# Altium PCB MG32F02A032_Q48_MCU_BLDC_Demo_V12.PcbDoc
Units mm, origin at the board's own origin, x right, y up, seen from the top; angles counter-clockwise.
Board outline 44 x 36.5 mm, 2 copper layers (TopLayer, BottomLayer); 27 components, 57 nets, 200 pads, 107 vias.
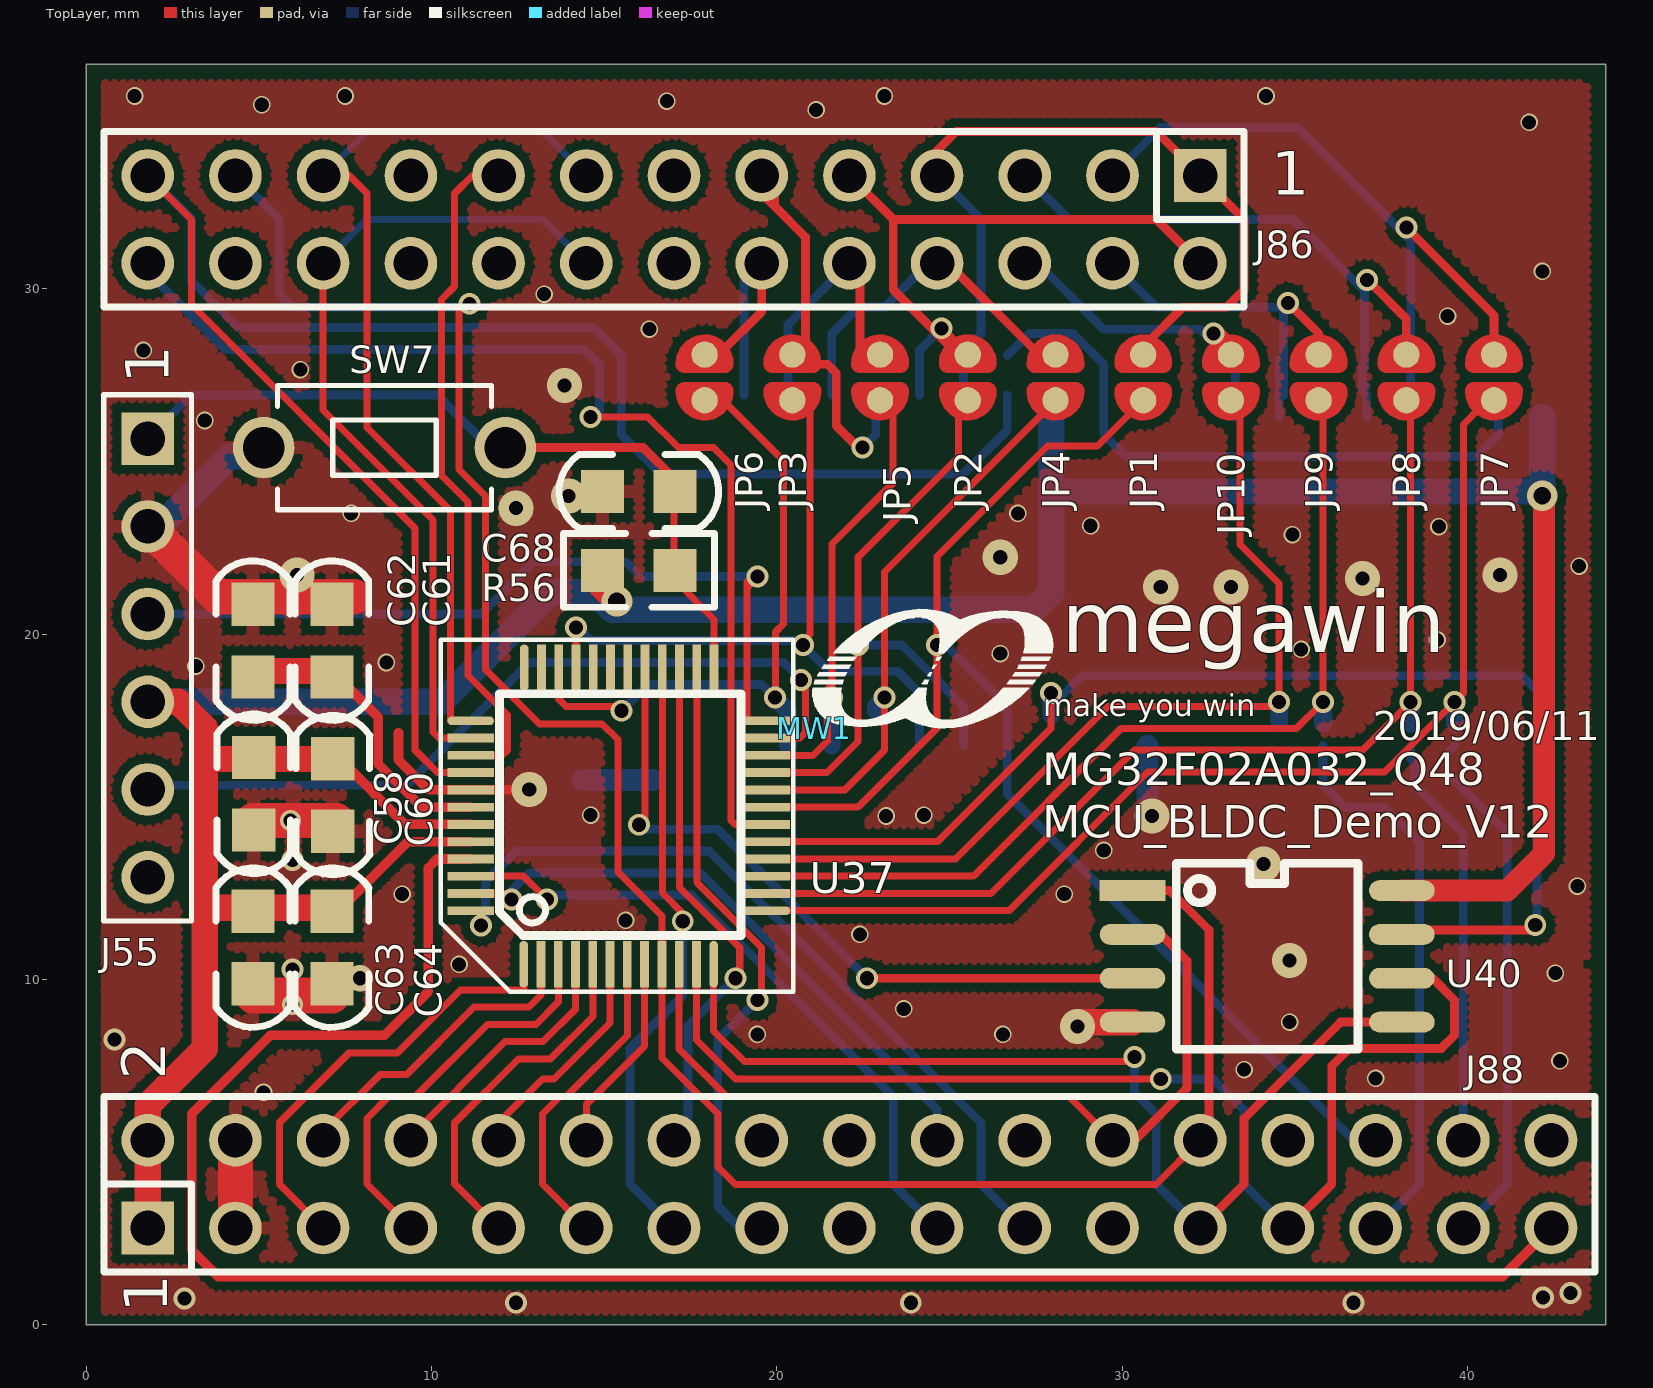
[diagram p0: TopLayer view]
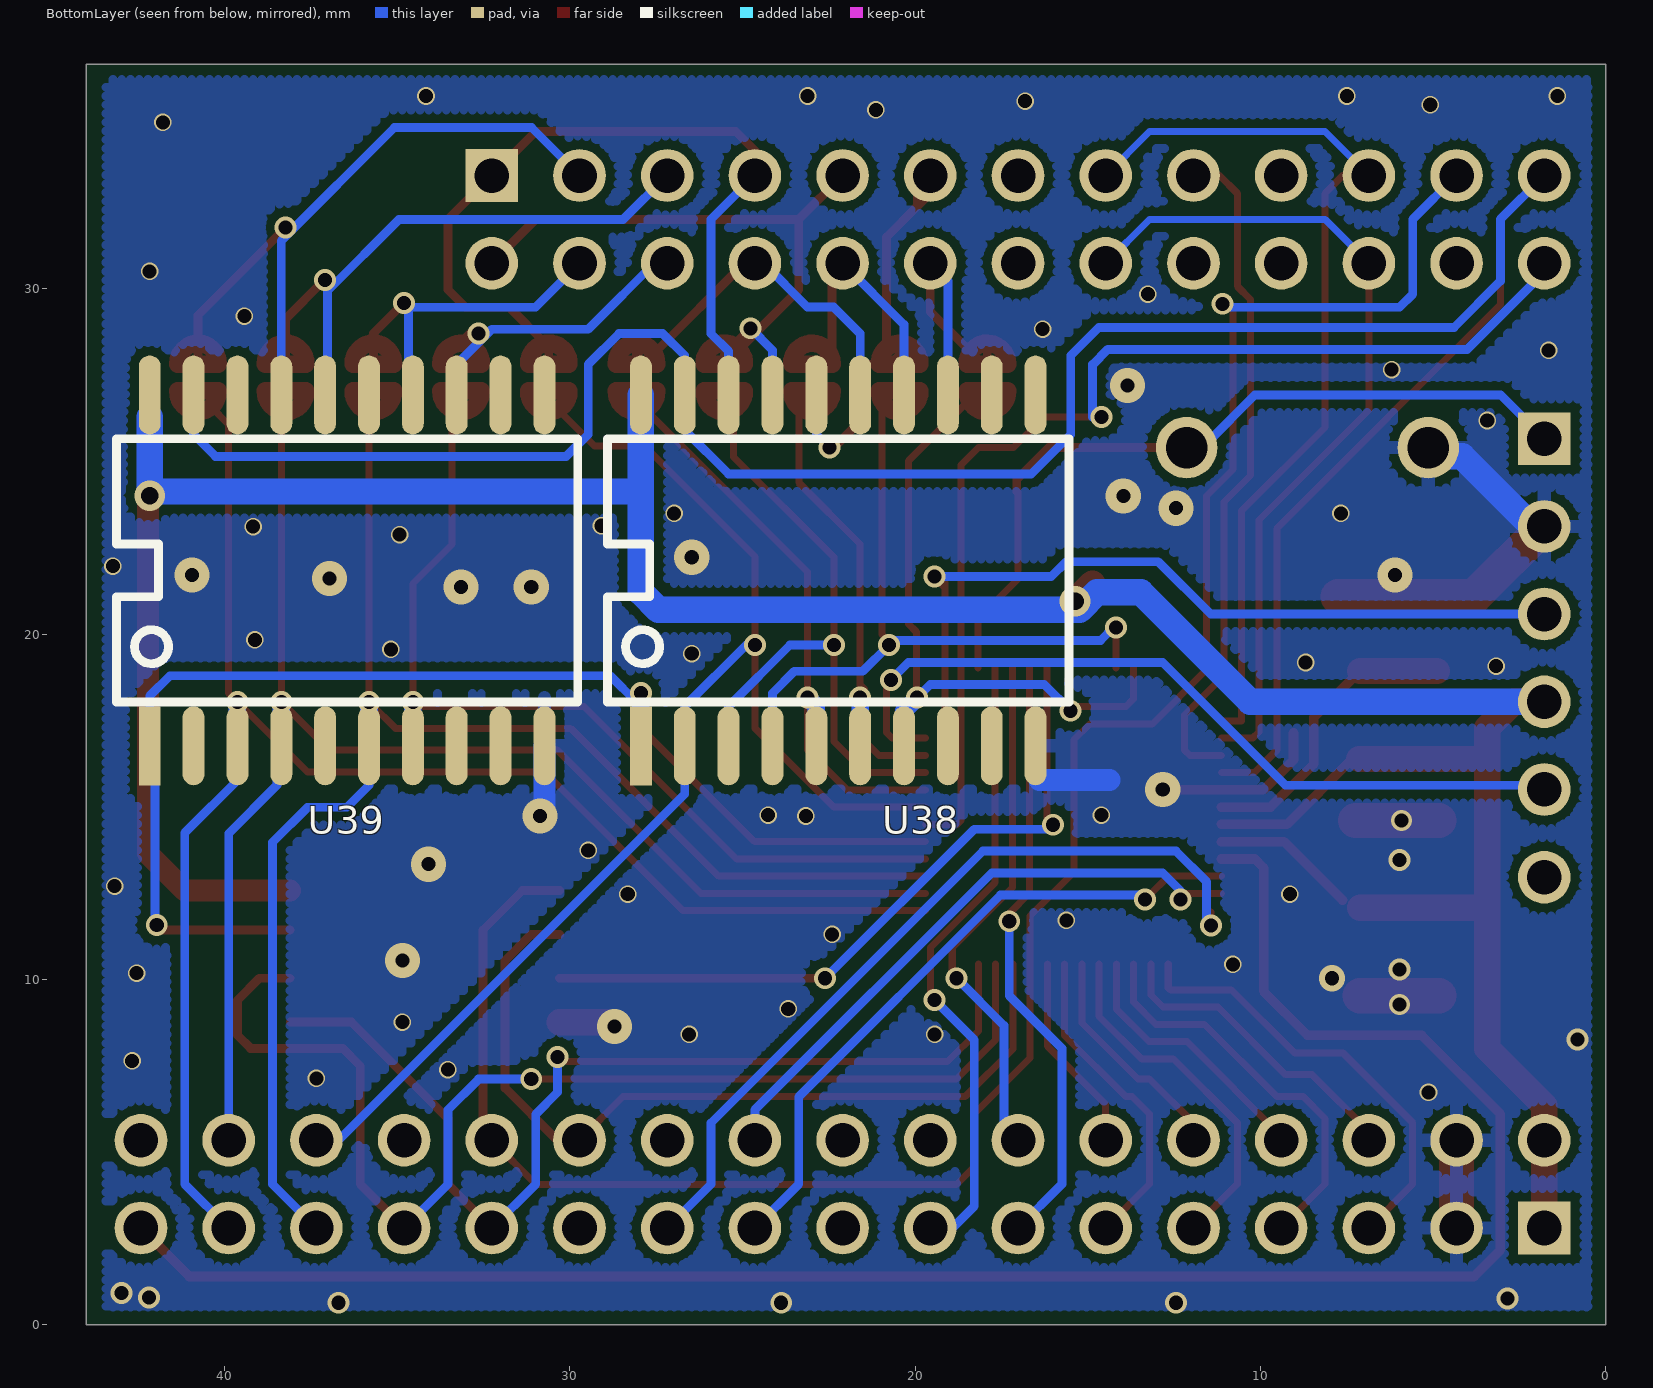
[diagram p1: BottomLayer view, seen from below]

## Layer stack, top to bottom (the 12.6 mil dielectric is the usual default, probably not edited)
TopLayer: signal copper 0.0356
Dielectric: dielectric 0.32, FR-4, Dk 4.8
BottomLayer: signal copper 0.0356

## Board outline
0,0 0,36.5 44,36.5 44,0

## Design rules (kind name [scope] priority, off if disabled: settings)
Clearance 12 [All] p1 off: gap=0.305
Clearance 10 [All] p2 off: gap=0.254
Clearance 6 [All] p3: gap=0.152
FabricationTestPointUsage TestPointUsage [All] p1: valid=0 allowmultiple=FALSE
FabricationTestpoint Testpoint [All] p1: side=3 testpointundercomponent=TRUE minsize=1.016 maxsize=2.54 preferedsize=1.524 minholesize=0.508 maxholesize=1.016 preferedholesize=0.813 testpointgrid=0.025 allowsidetop=TRUE allowsidebottom=TRUE usegrid=TRUE gridtolerance=0
HoleSize [All] p1: absolutevalues=TRUE maxlimit=12.7 minlimit=0.025 maxpercent=80.000 minpercent=20.000
PolygonConnect VIA [isvia] p1: connectstyle=Direct reliefconductorwidth=0.254 reliefentries=4 polygonreliefangle="90 Angle"
PolygonConnect PolygonConnect_1 [All] p2: connectstyle=Relief reliefconductorwidth=0.381 reliefentries=4 polygonreliefangle="90 Angle"
RoomDefinition MG32F02A032_Q48_MCU_BLDC_Demo_V12 [InComponentClass('MG32F02A032_Q48_MCU_BLDC_Demo_V12')] p1: confinementstyle=ConfineIn formatcopy=TRUE lockcomponents=FALSE outline -454.355,-362.943 -403.555,-362.943 -403.555,-337.543 -454.355,-337.543
RoutingPriority [All] p1: routingpriority=4
RoutingVias [All] p1: holewidth=0.406 width=0.635 viastyle="Through Hole" minholewidth=0.406 minwidth=0.61 maxholewidth=0.711 maxwidth=1.27
SilkscreenOverComponentPads [All] p1: minsilkscreentomaskgap=0.254
SolderMaskExpansion [All] p1: expansion=0.102
Width [All] p1: maxlimit=2.54 minlimit=0.203 preferedwidth=0.254
23 further rules are at their usual default settings.

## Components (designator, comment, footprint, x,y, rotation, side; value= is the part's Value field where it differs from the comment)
C58 "10u" 0805C 4.85,15.373 r270 top
C60 "0.1u" 0805C 7.136,15.339 r270 top
C61 "0.1u" 0805C 7.112,19.812 r90 top
C62 "4.7u" 0805C 4.826,19.812 r90 top
C63 "10u" 0805C 4.826,10.922 r270 top
C64 "0.1u" 0805C 7.112,10.922 r270 top
C68 "4.7u" 0805C 16.002,24.13 r180 top
J55 "ICE/Writer" PS6P254 1.778,25.66 r270 top
J86 "CON26A" PS13X2P254 32.258,33.28 r180 top locked
J88 "CON34A" PS17X2P254 1.778,2.8 r0 top locked
JP1 "SP" JUMP2C_SMD_1#1 30.607,27.432 r90 top
JP2 "SP" JUMP2C_SMD_1#2 25.527,27.432 r90 top
JP3 "SP" JUMP2C_SMD_1#3 20.447,27.432 r90 top
JP4 "SP" JUMP2C_SMD_1#4 28.067,27.432 r90 top
JP5 "SP" JUMP2C_SMD_1#5 22.987,27.432 r90 top
JP6 "SP" JUMP2C_SMD_1#6 17.907,27.432 r90 top
JP7 "SP" JUMP2C_SMD_1#7 40.767,27.432 r90 top
JP8 "SP" JUMP2C_SMD_1#8 38.227,27.432 r90 top
JP9 "SP" JUMP2C_SMD_1#9 35.687,27.432 r90 top
JP10 "SP" JUMP2C_SMD_1#10 33.147,27.432 r90 top
MW1 "MW-A4" MEGAWIN_3.4 21.082,17.272 r0 top
R56 "47K" 0805R 16.002,21.844 r0 top
SW7 "SW PUSHBUTTON" SW_T_2P 8.636,25.4 r180 top
U37 "MG32F02A032 QFP48" LQFP48_7X7_050 15.418,14.732 r0 top locked
U38 "74HC245/20P/SOIC" SO20_300P127 22.225,21.844 r180 bottom locked
U39 "74HC245/20P/SOIC" SO20_300P127 36.449,21.844 r180 bottom locked (schematic designator U38)
U40 "MX25L3206E/8-PIN SOP (200mil)" SO8_208P127 34.197,10.668 r270 top

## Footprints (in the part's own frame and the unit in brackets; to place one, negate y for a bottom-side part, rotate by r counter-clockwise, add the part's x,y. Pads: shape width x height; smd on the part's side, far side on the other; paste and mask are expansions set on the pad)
0805C [mm]
  rect 1.25x1.25 smd: 1(-1.05,0) 2(1.05,0)
  silkscreen extent -2.31,-1.07 2.31,1.07
0805R [mm]
  rect 1.25x1.25 smd: 1(-1.05,0) 2(1.05,0)
  silkscreen extent -2.18,-1.07 2.18,1.07
JUMP2C_SMD_1#1 [mil]
  round 30 smd: 1(-26,0) 2(26,0)
  TopLayer lines w20: -16,23 ccw(c-16,0) -29.57,18.57 ccw(c-16,0) -33.44,15 ccw(c-16,0) -34.57,13.57 ccw(c-16,0) -36.48,10.48 ccw(c-16,0) -38.45,5 ccw(c-16,0) -39,0 ccw(c-16,0) -16,-23 -15,-23 -15,0 -15,23 -16,23 ; 15,23 16,23 cw(c16,0) 26,20.71 cw(c16,0) 29.57,18.57 cw(c16,0) 34.57,13.57 cw(c16,0) 36.48,10.48 cw(c16,0) 38.7,-3.7 cw(c16,0) 36.48,-10.48 cw(c16,0) 16,-23 15,-23 15,0 15,23
JUMP2C_SMD_1#2 [mil]
  round 30 smd: 1(-26,0) 2(26,0)
  TopLayer lines w20: -16,23 ccw(c-16,0) -27.36,20 ccw(c-16,0) -33.44,15 ccw(c-16,0) -36.48,10.48 ccw(c-16,0) -36.71,10 ccw(c-16,0) -38.45,5 ccw(c-16,0) -39,0 ccw(c-16,0) -16,-23 -15,-23 -15,0 -15,15 -15,23 -16,23 ; 15,23 16,23 cw(c16,0) 26,20.71 cw(c16,0) 31.76,16.76 cw(c16,0) 33.44,15 cw(c16,0) 36.48,10.48 cw(c16,0) 38.45,5 cw(c16,0) 39,0 cw(c16,0) 26,-20.71 cw(c16,0) 16,-23 15,-23 15,0 15,23
JUMP2C_SMD_1#3 [mil]
  round 30 smd: 1(-26,0) 2(26,0)
  TopLayer lines w20: -16,23 ccw(c-16,0) -36.48,10.48 ccw(c-16,0) -38.9,2.1 ccw(c-16,0) -38.83,-2.83 ccw(c-16,0) -37.93,-6.93 ccw(c-16,0) -36.48,-10.48 ccw(c-16,0) -27.36,-20 ccw(c-16,0) -26,-20.71 ccw(c-16,0) -16,-23 -15,-23 -15,-20 -15,0 -15,23 -16,23 ; 15,23 15,20 15,0 15,-11 15,-15 15,-23 16,-23 ccw(c16,0) 28.98,-18.98 ccw(c16,0) 33.44,-15 ccw(c16,0) 36.48,-10.48 ccw(c16,0) 37.93,-6.93 ccw(c16,0) 38.9,2.1 ccw(c16,0) 36.48,10.48 ccw(c16,0) 27.36,20 ccw(c16,0) 16,23 15,23
JUMP2C_SMD_1#4 [mil]
  round 30 smd: 1(-26,0) 2(26,0)
  TopLayer lines w20: -16,23 ccw(c-16,0) -33.44,15 ccw(c-16,0) -36.71,10 ccw(c-16,0) -38.45,5 ccw(c-16,0) -39,0 ccw(c-16,0) -16,-23 -15,-23 -15,0 -15,15 -15,23 -16,23 ; 15,23 15,0 15,-23 16,-23 ccw(c16,0) 26,-20.71 ccw(c16,0) 39,0 ccw(c16,0) 36.48,10.48 ccw(c16,0) 36,11.36 ccw(c16,0) 27.36,20 ccw(c16,0) 26,20.71 ccw(c16,0) 16,23 15,23
JUMP2C_SMD_1#5 [mil]
  round 30 smd: 1(-26,0) 2(26,0)
  TopLayer lines w20: -16,23 ccw(c-16,0) -39,0 ccw(c-16,0) -33.44,-15 ccw(c-16,0) -16,-23 -15,-23 -15,-15 -15,0 -15,23 -16,23 ; 15,23 16,23 cw(c16,0) 29.12,-18.89 cw(c16,0) 16,-23 15,-23 15,0 15,23
JUMP2C_SMD_1#6 [mil]
  round 30 smd: 1(-26,0) 2(26,0)
  TopLayer lines w20: -16,23 ccw(c-16,0) -26,20.71 ccw(c-16,0) -38.96,1.33 ccw(c-16,0) -37.75,-7.47 ccw(c-16,0) -36.48,-10.48 ccw(c-16,0) -34.27,-13.98 ccw(c-16,0) -31.76,-16.76 ccw(c-16,0) -29.15,-18.87 ccw(c-16,0) -26,-20.71 ccw(c-16,0) -17.92,-22.92 ccw(c-16,0) -16,-23 -15,-23 -15,-20 -15,-11 -15,0 -15,23 -16,23 ; 15,23 15,0 15,-5 15,-23 16,-23 ccw(c16,0) 28.98,-18.98 ccw(c16,0) 36.48,-10.48 ccw(c16,0) 37.74,-7.5 ccw(c16,0) 38.73,-3.5 ccw(c16,0) 39,0 ccw(c16,0) 37.75,7.49 ccw(c16,0) 16,23 15,23
JUMP2C_SMD_1#7 [mil]
  round 30 smd: 1(-26,0) 2(26,0)
  TopLayer lines w20: -16,23 ccw(c-16,0) -33.44,15 ccw(c-16,0) -38.45,5 ccw(c-16,0) -39,0 ccw(c-16,0) -16,-23 -15,-23 -15,0 -15,23 -16,23 ; 15,23 15,0 15,-23 16,-23 ccw(c16,0) 39,0 ccw(c16,0) 38.45,5 ccw(c16,0) 38.16,6.16 ccw(c16,0) 33.44,15 ccw(c16,0) 16,23 15,23
JUMP2C_SMD_1#8 [mil]
  round 30 smd: 1(-26,0) 2(26,0)
  TopLayer lines w20: -16,23 ccw(c-16,0) -38.9,2.1 ccw(c-16,0) -39,0 ccw(c-16,0) -38.45,-5 ccw(c-16,0) -37.93,-6.93 ccw(c-16,0) -36.48,-10.48 ccw(c-16,0) -16,-23 -15,-23 -15,0 -15,23 -16,23 ; 15,23 15,0 15,-23 16,-23 ccw(c16,0) 39,0 ccw(c16,0) 16,23 15,23
JUMP2C_SMD_1#9 [mil]
  round 30 smd: 1(-26,0) 2(26,0)
  TopLayer lines w20: -16,23 ccw(c-16,0) -33.44,15 ccw(c-16,0) -38.45,5 ccw(c-16,0) -39,0 ccw(c-16,0) -38.45,-5 ccw(c-16,0) -16,-23 -15,-23 -15,0 -15,23 -16,23 ; 15,23 16,23 cw(c16,0) 39,0 cw(c16,0) 16,-23 15,-23 15,0 15,23
JUMP2C_SMD_1#10 [mil]
  round 30 smd: 1(-26,0) 2(26,0)
  TopLayer lines w20: -16,23 ccw(c-16,0) -33.44,15 ccw(c-16,0) -38.45,5 ccw(c-16,0) -38.9,2.1 ccw(c-16,0) -39,0 ccw(c-16,0) -37.93,-6.93 ccw(c-16,0) -36.48,-10.48 ccw(c-16,0) -16,-23 -15,-23 -15,0 -15,23 -16,23 ; 15,23 16,23 cw(c16,0) 28.98,18.98 cw(c16,0) 36.48,10.48 cw(c16,0) 30.5,-17.85 cw(c16,0) 16,-23 15,-23 15,0 15,23
LQFP48_7X7_050 [mm]
  oval 0.254x1.35 smd: 1(-2.75,-4.292) 12(2.75,-4.292) 36(-2.737,4.292)
  rect 0.254x1.35 smd: 2(-2.25,-4.292) 3(-1.75,-4.292) 4(-1.25,-4.292) 5(-0.75,-4.292) 6(-0.25,-4.292) 7(0.25,-4.292) 8(0.75,-4.292) 9(1.25,-4.292) 10(1.75,-4.292) 11(2.25,-4.292) 25(2.763,4.292) 26(2.263,4.292) 27(1.763,4.292) 28(1.263,4.292) 29(0.763,4.292) 30(0.263,4.292) 31(-0.237,4.292) 32(-0.737,4.292) 33(-1.237,4.292) 34(-1.737,4.292) 35(-2.237,4.292)
  oval 1.35x0.254 smd: 13(4.286,-2.744) 37(-4.286,2.756)
  rect 1.35x0.254 smd: 14(4.286,-2.244) 15(4.286,-1.744) 16(4.286,-1.244) 17(4.286,-0.744) 18(4.286,-0.244) 19(4.286,0.256) 20(4.286,0.756) 21(4.286,1.256) 22(4.286,1.756) 23(4.286,2.256) 24(4.286,2.756) 38(-4.286,2.256) 39(-4.286,1.756) 40(-4.286,1.256) 41(-4.286,0.756) 42(-4.286,0.256) 43(-4.286,-0.244) 44(-4.286,-0.744) 45(-4.286,-1.244) 46(-4.286,-1.744) 47(-4.286,-2.244) 48(-4.286,-2.744)
  silkscreen extent -5.15,-5.09 5.05,5.11
MEGAWIN_3.4 [mm]
  silkscreen extent -0.05,0.01 6.92,3.44
PS6P254 [mil]
  rect 60x60 hole 39.37: 1(0,0)
  round 60 hole 39.37: 2(100,0) 3(200,0) 4(300,0) 5(400,0) 6(500,0)
  silkscreen extent -50,-50 550,50
PS13X2P254 [mil]
  rect 60x60 hole 39.37: 1(0,0)
  round 60 hole 39.37: 2(0,100) 3(100,0) 4(100,100) 5(200,0) 6(200,100) 7(300,0) 8(300,100) 9(400,0) 10(400,100) 11(500,0) 12(500,100) 13(600,0) 14(600,100) 15(700,0) 16(700,100) 17(800,0) 18(800,100) 19(900,0) 20(900,100) 21(1000,0) 22(1000,100) 23(1100,0) 24(1100,100) 25(1200,0) 26(1200,100)
  silkscreen extent -50,-50 1250,150
PS17X2P254 [mil]
  rect 60x60 hole 39.37: 1(0,0)
  round 60 hole 39.37: 2(0,100) 3(100,0) 4(100,100) 5(200,0) 6(200,100) 7(300,0) 8(300,100) 9(400,0) 10(400,100) 11(500,0) 12(500,100) 13(600,0) 14(600,100) 15(700,0) 16(700,100) 17(800,0) 18(800,100) 19(900,0) 20(900,100) 21(1000,0) 22(1000,100) 23(1100,0) 24(1100,100) 25(1200,0) 26(1200,100) 27(1300,0) 28(1300,100) 29(1400,0) 30(1400,100) 31(1500,0) 32(1500,100) 33(1600,0) 34(1600,100)
  silkscreen extent -50,-50 1650,150
SO8_208P127 [mm]
  rect 0.6x1.9 smd: 1(-1.905,-3.9)
  oval 0.6x1.9 smd: 2(-0.635,-3.9) 3(0.635,-3.9) 4(1.905,-3.9) 5(1.905,3.9) 6(0.635,3.9) 7(-0.635,3.9) 8(-1.905,3.9)
  silkscreen extent -2.69,-2.63 2.69,2.63
SO20_300P127 [mil]
  rect 25x90 smd: 1(-225,-200)
  oval 25x90 smd: 2(-175,-200) 3(-125,-200) 4(-75,-200) 5(-25,-200) 6(25,-200) 7(75,-200) 8(125,-200) 9(175,-200) 10(225,-200) 11(225,200) 12(175,200) 13(125,200) 14(75,200) 15(25,200) 16(-25,200) 17(-75,200) 18(-125,200) 19(-175,200) 20(-225,200)
  silkscreen extent -263,-150 263,150
SW_T_2P [mm]
  round 1.778 hole 1.2: 1(-3.5,0) 2(3.5,0)
  silkscreen extent -3.1,-1.8 3.1,1.8

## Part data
C58 C60 C61 C62 C63 C64 C68: library part "CAP NP"
J55: library part CON6
MW1: library part MW_A4_1
R56: library part RESISTOR
U37: library part IC-MG32F02A-LQFP48
U38 U39: library part 74HC245_0
U40: library part MX25L3206E

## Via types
v1: diameter 0.508, hole 0.406, TopLayer to BottomLayer, tented both sides, 45 vias
v2: diameter 0.635, hole 0.406, TopLayer to BottomLayer, tented both sides, 43 vias
v3: diameter 1.016, hole 0.406, TopLayer to BottomLayer, tented both sides, 14 vias
v4: diameter 0.889, hole 0.508, TopLayer to BottomLayer, tented both sides, 2 vias
v5: diameter 0.61, hole 0.406, TopLayer to BottomLayer, tented both sides, 2 vias
v6: diameter 0.762, hole 0.406, TopLayer to BottomLayer, tented both sides, 1 vias

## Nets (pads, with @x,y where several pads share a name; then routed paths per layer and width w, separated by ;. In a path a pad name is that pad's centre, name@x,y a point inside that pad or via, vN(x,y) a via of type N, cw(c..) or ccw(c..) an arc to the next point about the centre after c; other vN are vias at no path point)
74HC245_DIR: U37.17 U38.1 U39.1 U40.7 | length 36.1
  TopLayer w0.203: U37.17 24.656,13.988 27.94,17.272 v2@27.94,18.034
  TopLayer w0.254: U40.7@38.097,11.43 v2@41.961,11.43
  BottomLayer w0.254: v2@28.067,18.034 28.829,18.796 41.579,18.796 42.164,18.211 U39.1 ; v2@42.012,11.58 U39.1@42.012,16.764
  BottomLayer w0.508: U38.1@27.94,17.653 v2(27.94,18.288)
  other v2: 41.961,11.58
ACM_UH: J86.1 J86.7 JP1.2 U38.18 | length 23.6
  TopLayer w0.254: J86.7@24.279,33.639 25.196,34.556 30.982,34.556 J86.1 33.528,32.01 33.528,29.972 33.02,29.464 31.75,29.464 30.701,28.415 30.607,28.321 JP1.2
  BottomLayer w0.254: J86.7 25.908,32.01 25.908,28.702 25.4,28.194 U38.18
ACM_UL: J86.8 JP4.2 U38.15 | length 11.9
  TopLayer w0.254: J86.8@24.638,31.242 J86.8 24.946,30.74 27.559,28.127 ; JP4.2@27.801,28.358 JP4.2 JP4.2@28.067,28.423
  BottomLayer w0.254: U38.15 21.59,28.702 22.358,29.47 23.114,29.47 24.384,30.74 J86.8 ; J86.8@24.384,30.486 J86.8 ; J86.8@24.638,31.369 J86.8
ACM_VH: J86.2 J86.9 JP2.2 U38.17 | length 19.3
  TopLayer w0.254: J86.9 23.368,32.01 ; 25.102,28.238 25.101,28.239 v2@24.484,28.856 ; JP2.2 25.261,28.358 v2(24.763,28.856) v2@24.484,28.856 ; J86.2 30.988,32.01 23.368,32.01 ; 23.368,32.01 23.368,29.972 v2@24.484,28.856
  BottomLayer w0.254: U38.17 24.13,28.222 v2(24.763,28.856)
ACM_VL: J86.10 JP5.2 U38.14 | length 7.8
  TopLayer w0.254: J86.10@22.098,30.124 J86.10 ; 22.403,27.838 J86.10@22.403,30.48
  BottomLayer w0.254: U38.14 20.32,28.962 J86.10
ACM_WH: J86.11 JP3.2 U38.16 | length 11.7
  TopLayer w0.254: J86.11@19.558,32.766 19.939,32.385 ; 19.939,32.379 19.939,32.385 ; J86.11@19.939,32.893 19.939,32.385 ; JP3.2 20.726,27.813 20.828,27.813 ; v2(22.479,25.4) 22.352,25.4 21.717,26.035 21.717,27.559 21.463,27.813 21.031,27.813 20.828,27.813 ; 19.939,32.385 20.828,31.496 20.828,28.281 20.828,27.813
  BottomLayer w0.254: v2(22.479,25.4) 22.86,25.781 U38.16
ACM_WL: J86.12 JP6.2 U38.13 | length 8.5
  TopLayer w0.254: 17.907,27.686 18.034,27.813 18.389,28.168 19.558,29.337 J86.12 J86.12@19.158,30.74 ; JP6.2 JP6.2@17.907,28.423
  BottomLayer w0.254: U38.13 19.05,30.232 J86.12
ADC_VR_IN: J88.33 U37.45 | length 57.4
  TopLayer w0.279: U37.45 10.161,13.488 9.906,13.233 9.906,9.652 8.636,8.382 5.334,8.382 3.048,6.096 3.048,2.159 3.81,1.397 41.015,1.397 J88.33
BLDC_VH: J86.3 JP7.2 U39.17 | length 20.4
  TopLayer w0.254: v2(38.227,31.773) 40.767,29.233 40.767,28.423 JP7.2
  BottomLayer w0.254: J86.3 31.109,34.671 35.075,34.671 38.354,31.392 U39.17 U39.17@38.354,26.289
BLDC_VL: J86.4 JP9.2 U39.14 | length 12.2
  TopLayer w0.254: J86.4 J86.4@30.22,30.74 ; v2@34.662,29.732 35.687,28.706 35.687,28.423 JP9.2
  BottomLayer w0.254: J86.4 30.994,29.464 34.671,29.464 U39.14@34.671,26.924 ; U39.14@34.544,26.289 U39.14 U39.14@34.544,27.94
  other v2: 34.798,29.591
BLDC_WH: J86.5 JP8.2 U39.16 | length 17.6
  TopLayer w0.254: v2@37.135,30.226 38.227,29.134 38.227,28.423 JP8.2
  BottomLayer w0.254: J86.5 28.448,32.01 34.942,32.01 37.016,29.936 U39.16@37.016,27.709 ; U39.16@36.957,27.813 36.957,27.051 U39.16@37.084,27.178 ; U39.16@37.084,26.289 U39.16
  other v2: 37.084,30.249
BLDC_WL: J86.6 JP10.2 U39.13 | length 10.7
  TopLayer w0.254: J86.6 J86.6@27.68,30.74 ; v2@32.766,28.829 JP10.2@33.147,28.448
  BottomLayer w0.254: J86.6@27.178,30.226 J86.6 27.178,30.988 27.302,30.864 27.429,30.864 29.464,28.829 32.258,28.829 33.274,27.813 U39.13 U39.13@33.274,26.289
  other v2: 32.639,28.702
FAULT: J86.26 U37.18 | length 31.7
  TopLayer w0.203: v2@14.859,26.289 16.256,26.289 17.145,25.4 18.161,25.4 18.669,24.892 18.669,14.605 18.786,14.488 U37.18
  BottomLayer w0.254: J86.26 1.778,30.48 4.013,28.245 14.418,28.245 14.859,27.804 v2@14.859,26.289
  other v2: 14.605,26.289
GND: C58.2 C60.2 C61.2 C62.2 C63.2 C64.2 C68.2 J55.2 J88.3 J88.4 SW7.2 U37.41 U38.10 U39.10 U40.4 | length 28.6
  TopLayer w0.279: 9.042,17.145 9.042,16.358 9.912,15.488 U37.41 12.309,15.488
  TopLayer w0.762: v3@28.829,8.763 U40.4
  TopLayer w1.016: J55.2 3.816,21.082 7.747,21.082 ; J88.3 J88.4 ; C63.2@4.826,9.525 C64.2@7.112,9.525 ; C58.2@4.826,14.605 v5(5.917,14.605) C60.2@7.239,14.605
  BottomLayer w0.254: v3@30.734,14.859 v3(30.861,14.732)
  BottomLayer w0.635: 14.371,15.771 U38.10@16.403,15.771 ; v3@30.734,14.859 U39.10
  BottomLayer w0.762: J55.2@1.893,22.885 4.153,25.146 SW7.2@5.207,25.146
  BottomLayer w1.016: J88.4 J88.4@4.318,5.594
  other v1: 5.131,6.731 37.338,7.135 33.528,7.389 42.672,7.643 19.431,8.405 26.543,8.405 34.849,8.763 23.673,9.144 42.545,10.183 10.795,10.437 22.403,11.303 15.621,11.707 9.144,12.469 28.321,12.469 43.18,12.7 29.464,13.739 23.165,14.732 14.605,14.755 24.257,14.755 3.175,19.073 8.687,19.177 26.467,19.431 35.179,19.558 39.116,19.835 43.231,21.971 34.925,22.883 39.167,23.114 29.083,23.137 7.671,23.495 26.975,23.495 3.429,26.185 6.198,27.661 1.651,28.217 16.307,28.829 39.421,29.21 13.259,29.845 42.164,30.503 41.783,34.821 21.133,35.179 5.08,35.329 16.815,35.433 1.397,35.583 7.493,35.583 23.114,35.583 34.163,35.583
  other v2: 12.446,0.635 23.876,0.635 36.703,0.635 2.845,0.762 42.189,0.785 42.977,0.914 0.813,8.255 5.969,10.287 5.969,13.462
  other v3: 28.702,8.636 34.849,10.541 34.087,13.335 12.827,15.494 31.115,21.359 33.147,21.359 36.957,21.613 6.096,21.717 40.945,21.717 26.467,22.225 12.446,23.645 13.97,24.003 13.843,27.201
  other v5: 5.969,9.271
  other v6: 7.925,10.033
GPIOA_P1: J88.19 U37.46 | length 19.3
  TopLayer w0.203: U37.46 12.666,12.988 13.208,12.446 v2@13.462,12.446
  BottomLayer w0.254: v2@13.335,12.446 17.526,12.446 23.368,6.604 23.368,4.07 J88.19
  other v2: 13.335,12.319
GPIOA_P2: J88.20 U37.47 | length 17.8
  TopLayer w0.203: U37.47 12.15,12.488 v2(12.319,12.319)
  BottomLayer w0.254: v2(12.319,12.319) 12.319,12.573 12.827,13.081 17.78,13.081 24.638,6.223 J88.20
GPIOA_P3: J88.21 U37.48 | length 23
  TopLayer w0.203: v2@11.43,11.684 U37.48@11.43,11.944
  BottomLayer w0.254: v2@11.557,11.684 11.557,12.827 12.446,13.716 18.034,13.716 25.908,5.842 25.908,4.07 J88.21
  other v2: 11.43,11.557
GPIOA_P8: J88.5 U37.1 | length 13
  TopLayer w0.203: J88.5 5.588,4.07 5.588,5.848 7.614,7.874 9.017,7.874 10.839,9.696 12.608,9.696 12.668,9.756 U37.1
GPIOA_P9: J88.6 U37.2 | length 9.1
  TopLayer w0.203: J88.6 6.858,5.594 8.503,7.239 9.271,7.239 11.228,9.196 12.815,9.196 13.168,9.549 U37.2
GPIOA_P10: J88.7 U37.3 | length 11.7
  TopLayer w0.203: J88.7 8.128,4.07 8.128,5.975 8.757,6.604 9.525,6.604 11.617,8.696 13.022,8.696 13.668,9.342 U37.3
GPIOA_P11: J88.8 U37.4 | length 7.7
  TopLayer w0.203: J88.8 9.398,5.467 12.127,8.196 13.229,8.196 14.168,9.134 U37.4
GPIOA_P12: J88.9 U37.5 | length 10.4
  TopLayer w0.203: J88.9 10.668,4.07 10.668,5.848 12.516,7.696 13.437,7.696 14.668,8.927 U37.5
GPIOA_P13: J88.10 U37.6 | length 6.6
  TopLayer w0.203: J88.10 11.938,5.848 13.208,7.118 13.544,7.118 15.168,8.742 U37.6
GPIOA_P14: J88.11 U37.7 | length 9.3
  TopLayer w0.203: J88.11 13.208,4.07 13.208,6.102 13.716,6.61 13.9,6.61 15.668,8.378 U37.7
GPIOA_P15: J88.12 U37.8 | length 5.8
  TopLayer w0.203: J88.12 14.478,6.375 16.168,8.065 U37.8
GPIOB_P0: J86.23 J88.26 U37.9 U40.1 | length 62.4
  TopLayer w0.203: 10.795,29.439 10.795,24.765 11.557,24.003 11.557,18.97 13.128,17.399 14.935,17.399 15.392,16.942 15.392,13.106 16.668,11.831 U37.9 16.668,7.722 18.288,6.102 18.288,4.572 18.796,4.064 30.982,4.064 J88.26 ; J88.26@32.258,5.461 J88.26 ; J88.26@32.512,5.594 J88.26
  TopLayer w0.254: U40.1 31.369,12.573 32.512,11.43 J88.26@32.512,5.594
  BottomLayer w0.203: v2@10.998,29.464 v2(11.1,29.566)
  BottomLayer w0.254: J86.23 5.588,32.01 5.588,29.845 5.969,29.464 v2@10.998,29.464
GPIOB_P1: J88.24 U37.10 U40.2 | length 24.5
  TopLayer w0.203: U37.10 17.168,7.984 18.548,6.604 28.454,6.604 J88.24 J88.24@30.359,5.34
  TopLayer w0.254: U40.2 31.115,11.303 31.877,10.541 31.877,6.858 J88.24@30.359,5.34
GPIOB_P2: J88.27 U37.11 U40.6 | length 34.8
  TopLayer w0.203: U37.11 17.668,8.246 18.802,7.112 30.988,7.112 v2@31.051,7.175
  TopLayer w0.254: J88.27 36.068,4.07 36.068,7.493 36.576,8.001 39.243,8.001 39.624,8.382 39.624,9.398 38.989,10.033 U40.6
  BottomLayer w0.254: v2(31.115,7.112) 32.639,7.112 33.528,6.223 33.528,4.07 J88.27
GPIOB_P3: J88.25 U37.12 U40.5 | length 29.9
  TopLayer w0.203: U37.12 18.168,8.508 19.056,7.62 30.099,7.62 v2@30.353,7.874
  TopLayer w0.254: J88.25 33.528,4.07 33.528,5.969 36.322,8.763 U40.5
  BottomLayer w0.254: v2@30.353,7.874 v2(30.353,7.747) 30.353,6.731 30.988,6.096 30.988,4.07 J88.25
GPIOB_P8: J88.31 JP7.1 U37.13 U39.3 | length 46.6
  TopLayer w0.203: U37.13 26.72,11.988 30.734,16.002 37.592,16.002 v2(39.624,18.034) 39.878,18.288 39.878,26.075 40.386,26.583 ; J88.31@39.624,2.8 J88.31
  BottomLayer w0.254: U39.3@39.497,16.637 U39.3 ; U39.3@39.548,15.842 41.148,14.242 41.148,4.07 J88.31
  BottomLayer w0.508: U39.3@39.624,17.399 v2(39.624,18.034)
GPIOB_P9: J88.32 JP8.1 U37.14 U39.4 | length 49.2
  TopLayer w0.203: U37.14 26.204,12.488 30.353,16.637 36.957,16.637 v2(38.354,18.034) 38.354,18.796 ; 38.354,25.756 38.354,18.796 ; JP8.1@38.354,26.645 38.354,26.455 38.354,18.796
  BottomLayer w0.254: U39.4 38.354,16.383 38.481,16.256 38.481,15.621 39.878,14.224 J88.32
  BottomLayer w0.508: U39.4@38.354,17.399 v2(38.354,18.034)
GPIOB_P10: J88.29 JP9.1 U37.15 U39.6 | length 44
  TopLayer w0.203: U37.15 25.688,12.988 29.972,17.272 35.052,17.272 v2@35.75,17.97 ; JP9.1 35.814,26.645 35.814,26.455 v2(35.814,18.034) v2@35.75,17.97 ; v2@35.75,18.034 v2@35.75,17.97
  BottomLayer w0.254: U39.6 35.814,15.621 36.449,14.986 37.592,14.986 38.608,13.97 38.608,4.07 J88.29
  BottomLayer w0.508: U39.6@35.814,17.399 v2(35.814,18.034)
GPIOB_P11: JP10.1 U37.16 U39.7 | length 26.8
  TopLayer w0.203: U37.16 25.172,13.488 29.591,17.907 34.417,17.907 v2(34.544,18.034) 34.544,21.463 33.413,22.594 JP10.1@33.413,26.506 ; JP10.1 JP10.1@33.413,26.506 ; JP10.1@33.351,26.568 JP10.1@33.413,26.506
  BottomLayer w0.508: U39.7@34.544,17.399 v2(34.544,18.034)
GPIOC_P0: J88.30 JP1.1 U37.19 U38.2 | length 38.6
  TopLayer w0.203: U37.19 22.354,14.988 24.638,17.272 v2(24.638,19.685) 24.638,22.248 27.837,25.447 29.283,25.447 30.341,26.506 JP1.1
  BottomLayer w0.254: v2@24.892,19.685 26.67,17.907 U38.2 26.67,15.367 36.697,5.34 J88.30
GPIOC_P1: JP4.1 U37.20 U38.5 | length 16.5
  TopLayer w0.203: U37.20 21.965,15.488 23.114,16.637 v2(23.114,18.161) 23.114,21.801 27.813,26.5 27.813,26.67 27.686,26.797
  BottomLayer w0.508: U38.5@22.86,17.78 22.86,17.907 v2(23.114,18.161)
GPIOC_P2: JP2.1 U37.21 U38.3 | length 19.1
  TopLayer w0.203: U37.21 21.449,15.988 22.352,16.891 v2(22.352,19.685) 22.352,22.225 25.261,25.134 25.261,26.506 JP2.1
  BottomLayer w0.254: v2@22.385,19.685 23.622,19.685 25.4,17.907 U38.3
GPIOC_P3: JP5.1 U37.22 U38.6 | length 14.7
  TopLayer w0.203: U37.22 21.049,16.488 21.463,16.903 21.463,18.415 21.59,18.542 ; v2(21.59,18.161) 21.59,18.542 ; JP5.1 23.368,26.772 23.368,26.583 23.368,24.384 21.59,22.606 21.59,18.542
  BottomLayer w0.508: U38.6 v2(21.59,18.161)
GPIOC_P4: J55.5 U37.23 | length 23.4
  TopLayer w0.203: U37.23 20.671,16.988 20.828,17.145 v2@20.828,18.669
  BottomLayer w0.254: J55.5 1.902,15.624 9.274,15.624 12.827,19.177 20.193,19.177 v2(20.701,18.669)
GPIOC_P5: J55.3 U37.24 | length 22.8
  TopLayer w0.203: U37.24@19.126,17.475 19.126,21.336 ; v2@19.304,21.514 19.126,21.336 ; v2@19.304,21.666 19.126,21.488 19.126,21.336
  BottomLayer w0.254: J55.3 11.436,20.58 12.954,22.098 15.621,22.098 16.053,21.666 v2@19.304,21.666
  other v2: 19.431,21.666
GPIOC_P6: C68.1 J55.1 R56.2 SW7.1 U37.25 | length 23.3
  TopLayer w0.203: R56.2@17.018,21.59 18.181,20.427 U37.25 ; R56.2@17.018,21.844 C68.1@17.018,24.13
  TopLayer w0.254: SW7.1 16.129,25.4 17.052,24.477 C68.1
  BottomLayer w0.254: J55.1 3.042,26.924 10.16,26.924 11.557,25.527 12.771,25.527 SW7.1@12.898,25.4
GPIOC_P8: J88.15 U37.26 | length 18.2
  TopLayer w0.203: U37.26 17.68,12.8 19.558,10.922 v2@19.558,9.398
  BottomLayer w0.254: J88.15@19.253,2.464 18.288,3.429 18.288,8.255 v2(19.431,9.398)
GPIOC_P9: J88.14 U37.27 | length 14.6
  TopLayer w0.203: U37.27 17.18,12.665 18.923,10.922 v2@18.923,10.033
  BottomLayer w0.254: J88.14@17.424,5.67 17.424,8.661 v2(18.796,10.033)
GPIOC_P10: J88.13 U37.28 | length 17.6
  TopLayer w0.203: U37.28 16.68,12.504 17.272,11.913 v2(17.272,11.684)
  BottomLayer w0.254: J88.13 15.748,4.07 15.748,8.001 17.272,9.525 v2(17.272,11.684)
GPIOC_P11: U37.29 U40.3 | length 20.6
  TopLayer w0.203: v2@16.18,14.478 U37.29
  TopLayer w0.254: v2(22.606,10.033) U40.3
  BottomLayer w0.254: v2@16.002,14.351 18.288,14.351 v2(22.606,10.033)
  other v2: 16.002,14.478
GPIOC_P12: U37.30
GPIOC_P13: U37.31
GPIOC_P14: U37.32
GPIOD_P0: JP3.1 U37.33 U38.4 | length 20.6
  TopLayer w0.203: U37.33 v2(14.18,20.193) v2@14.18,20.269 ; v2@20.777,19.812 20.955,19.99 20.955,26.737 20.955,26.949
  BottomLayer w0.254: v2@14.249,20.193 14.63,19.812 v2@20.752,19.812 ; v2(20.752,19.685) 21.513,18.924 23.494,18.924 24.13,18.288 U38.4
GPIOD_P1: JP6.1 U37.34 U38.7 | length 19
  TopLayer w0.203: U37.34 13.68,18.12 13.894,17.907 v2@15.367,17.907 ; JP6.1 18.433,26.772 18.44,26.772 20.193,25.019 20.193,20.295 19.964,20.066 v2@19.964,18.415
  TopLayer w0.254: v2@15.367,17.907 v2(15.494,17.78)
  BottomLayer w0.254: v2(15.494,17.78) 16.256,18.542 19.558,18.542 v2(19.939,18.161)
  BottomLayer w0.508: v2(19.939,18.161) 20.32,17.78 U38.7
GPIOD_P2: U37.35
GPIOD_P3: U37.36
GPIOD_P7: J86.15 J86.21 U37.37 | length 27
  TopLayer w0.203: J86.21 7.614,33.28 8.128,32.766 8.128,25.984 10.541,23.571 10.541,17.488 U37.37
  BottomLayer w0.203: J86.21 8.128,34.55 13.208,34.55 J86.15
GPIOD_P8: J86.16 J86.22 U37.38 | length 24.7
  TopLayer w0.203: J86.22 6.858,26.492 10.041,23.309 10.041,17.166 10.219,16.988 U37.38
  BottomLayer w0.203: J86.22 8.122,32.004 13.214,32.004 J86.16
GPIOD_P9: J86.17 U37.39 | length 19.7
  TopLayer w0.203: U37.39 12.043,16.488 12.192,16.637 12.192,17.653 11.049,18.796 11.049,23.825 10.287,24.587 10.287,29.693 10.668,30.074 10.668,32.766 11.182,33.28 J86.17
GPIOD_P10: J86.25 U37.40 U38.19 U39.19 | length 72.7
  TopLayer w0.203: J86.25 3.048,32.01 3.048,29.54 9.525,23.063 9.525,16.637 10.174,15.988 U37.40
  BottomLayer w0.254: J86.25 3.048,32.01 3.048,30.226 4.394,28.88 14.681,28.88 15.494,28.067 15.494,25.781 16.637,24.638 25.4,24.638 26.67,25.908 U38.19 ; 26.67,28.067 27.305,28.702 28.575,28.702 29.464,27.813 29.464,25.781 30.099,25.146 40.259,25.146 40.894,25.781 U39.19
NetC61_1: C61.1 C62.1 U37.42 | length 8.6
  TopLayer w0.279: C61.1@7.196,18.845 8.458,17.583 8.458,16.231 9.7,14.988 U37.42
  TopLayer w0.762: C62.1@4.884,18.929 C61.1@7.112,18.929
VDD5V: C58.1 C60.1 C63.1 C64.1 J55.4 J88.1 J88.2 R56.1 U37.43 U37.44 U38.20 U39.20 U40.8 | length 99.3
  TopLayer w0.279: C60.1@7.136,16.383 7.341,16.383 9.235,14.488 U37.43 ; C64.1@7.62,12.294 9.315,13.988 U37.44
  TopLayer w0.635: U40.8 41.148,12.573 42.215,13.64 v4@42.215,24.003
  TopLayer w0.762: J88.1 J88.2 1.778,6.35 3.429,8.001 3.429,12.071 ; J55.4 2.667,18.04 3.429,17.278 3.429,16.383 ; C64.1@7.112,12.071 3.429,12.071 ; C60.1@7.136,16.383 3.429,16.383 ; R56.1@14.859,21.463 v4(15.367,20.955) ; 3.429,12.071 3.429,16.383
  BottomLayer w0.508: J55.4 J55.4@1.848,18.11 ; J55.4@1.918,18.04 J55.4@1.918,18.097
  BottomLayer w0.762: J55.4 1.918,18.04 10.293,18.04 13.462,21.209 14.732,21.209 15.24,20.701 27.432,20.701 27.94,21.209 27.94,24.13 ; U38.20 27.94,24.13 ; U39.20@42.164,26.289 42.164,24.13 27.94,24.13
  other v4: 42.164,24.003
pads on no net: J55.6 J86.13 J86.14 J86.18 J86.19 J86.20 J86.24 J88.16 J88.17 J88.18 J88.22 J88.23 J88.28 J88.34 U38.8 U38.9 U38.11 U38.12 U39.2 U39.5 U39.8 U39.9 U39.11 U39.12 U39.15 U39.18

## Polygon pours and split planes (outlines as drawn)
GND on TopLayer "Top Layer-No Net" (hatched 90Degree grid 0.254 track 0.254, remove dead copper, pour order 1001): 0.533,0.381 43.459,0.381 43.459,35.941 0.533,35.941
GND on BottomLayer "Top Layer-No Net" (hatched 90Degree grid 0.254 track 0.254, remove dead copper, pour order 1000): 0.508,0.508 43.434,0.508 43.434,36.068 0.508,36.068

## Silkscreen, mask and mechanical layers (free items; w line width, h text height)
TopOverlay:
  text "1" at 34.316,32.725 h1.27
  text "1" at 2.388,27.254 h1.27 r90
  text "2019/06/11" at 37.249,16.929 h0.84
  text "MG32F02A032_Q48" at 27.686,15.621 h0.94
  text "MCU_BLDC_Demo_V12" at 27.686,14.097 h0.94
  text "2" at 2.286,7.096 h1.27 r90
  text "1" at 2.337,0.34 h1.27 r90
Mechanical1:
  the board outline again, w0.203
